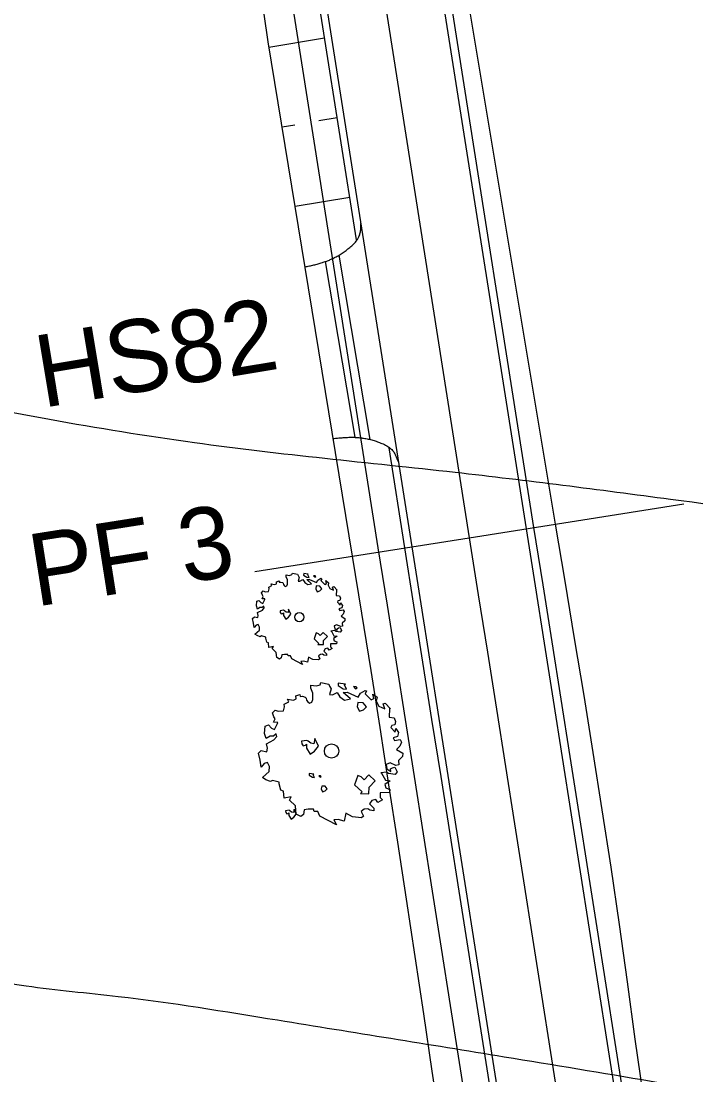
# Model space of a CAD drawing. Extents: x -477701 to -476785, y -1116511 to -1115314.
# Drawn here: x -477316.99 to -477293.68, y -1116152.79 to -1116116.39 of the extents above; entities that cross this region are included whole.
import ezdxf

# ---------------------------------------------------------------- set-up
doc = ezdxf.new("R2010")
doc.units = 0
for name, color, linetype in [('hrana_P', 7, 'Continuous'), ('hrana_R', 7, 'Continuous'), ('IP_RBK', 7, 'Continuous'), ('POLYGONY_SITUACE_PF', 7, 'Continuous'), ('POLYGONY_SITUACE_PF_POPISY', 7, 'Continuous'), ('popis', 7, 'Continuous'), ('svahování', 7, 'Continuous'), ('TP_HS', 7, 'Continuous'), ('Vrstevnice_hlavni', 7, 'Continuous'), ('Vrstevnice_vedlejsi', 7, 'Continuous')]:
    doc.layers.add(name, color=color, linetype=linetype)

msp = doc.modelspace()

# ---------------------------------------------------------------- linework, layer by layer
at = {"layer": 'hrana_P'}
for points in [[(-477308.462, -1116117.111), (-477310.173, -1116105.232)], [(-477298.532, -1116133.768), (-477301.498, -1116116.013)], [(-477305.541, -1116134.873), (-477308.462, -1116117.111)], [(-477298.196, -1116135.739), (-477298.532, -1116133.768)], [(-477305.218, -1116136.846), (-477305.541, -1116134.873)], [(-477297.882, -1116137.715), (-477298.196, -1116135.739)], [(-477304.905, -1116138.822), (-477305.218, -1116136.846)], [(-477297.547, -1116139.686), (-477297.882, -1116137.715)], [(-477304.593, -1116140.797), (-477304.905, -1116138.822)], [(-477297.23, -1116141.661), (-477297.547, -1116139.686)], [(-477304.289, -1116142.774), (-477304.593, -1116140.797)], [(-477296.917, -1116143.637), (-477297.23, -1116141.661)], [(-477303.984, -1116144.751), (-477304.289, -1116142.774)], [(-477296.617, -1116145.614), (-477296.917, -1116143.637)], [(-477303.678, -1116146.727), (-477303.984, -1116144.751)], [(-477296.328, -1116147.593), (-477296.617, -1116145.614)], [(-477303.378, -1116148.704), (-477303.678, -1116146.727)], [(-477296.045, -1116149.573), (-477296.328, -1116147.593)], [(-477303.079, -1116150.682), (-477303.378, -1116148.704)], [(-477295.781, -1116151.556), (-477296.045, -1116149.573)], [(-477302.79, -1116152.661), (-477303.079, -1116150.682)], [(-477293.766, -1116165.412), (-477295.781, -1116151.556)], [(-477300.647, -1116166.496), (-477302.79, -1116152.661)]]:
    msp.add_lwpolyline(points, dxfattribs=at)
at = {"layer": 'hrana_R'}
for points in [[(-477306.183, -1116104.603), (-477304.314, -1116116.457)], [(-477307.456, -1116116.807), (-477309.324, -1116104.954)], [(-477306.537, -1116116.807), (-477308.405, -1116104.954)], [(-477306.29, -1116116.768), (-477308.159, -1116104.915)], [(-477302.092, -1116116.107), (-477299.289, -1116133.887)], [(-477304.314, -1116116.457), (-477301.511, -1116134.237)], [(-477299.536, -1116133.926), (-477302.339, -1116116.145)], [(-477304.653, -1116134.588), (-477307.456, -1116116.807)], [(-477305.412, -1116123.945), (-477306.537, -1116116.807)], [(-477303.487, -1116134.549), (-477306.29, -1116116.768)], [(-477303.734, -1116134.588), (-477304.279, -1116131.133)], [(-477299.224, -1116135.901), (-477299.536, -1116133.926)], [(-477299.289, -1116133.887), (-477298.977, -1116135.863)], [(-477301.511, -1116134.237), (-477301.2, -1116136.213)], [(-477304.341, -1116136.563), (-477304.653, -1116134.588)], [(-477303.422, -1116136.563), (-477303.734, -1116134.588)], [(-477303.175, -1116136.524), (-477303.487, -1116134.549)], [(-477298.913, -1116137.877), (-477299.224, -1116135.901)], [(-477298.977, -1116135.863), (-477298.666, -1116137.838)], [(-477301.2, -1116136.213), (-477300.888, -1116138.189)], [(-477304.03, -1116138.539), (-477304.341, -1116136.563)], [(-477303.111, -1116138.539), (-477303.422, -1116136.563)], [(-477302.864, -1116138.5), (-477303.175, -1116136.524)], [(-477298.601, -1116139.853), (-477298.913, -1116137.877)], [(-477298.666, -1116137.838), (-477298.354, -1116139.814)], [(-477300.888, -1116138.189), (-477300.577, -1116140.164)], [(-477303.718, -1116140.514), (-477304.03, -1116138.539)], [(-477302.799, -1116140.514), (-477303.111, -1116138.539)], [(-477302.552, -1116140.476), (-477302.864, -1116138.5)], [(-477298.29, -1116141.828), (-477298.601, -1116139.853)], [(-477298.354, -1116139.814), (-477298.043, -1116141.789)], [(-477303.407, -1116142.49), (-477303.718, -1116140.514)], [(-477302.488, -1116142.49), (-477302.799, -1116140.514)], [(-477302.241, -1116142.451), (-477302.552, -1116140.476)], [(-477300.577, -1116140.164), (-477300.265, -1116142.14)], [(-477297.978, -1116143.804), (-477298.29, -1116141.828)], [(-477298.043, -1116141.789), (-477297.731, -1116143.765)], [(-477300.265, -1116142.14), (-477299.954, -1116144.115)], [(-477303.095, -1116144.466), (-477303.407, -1116142.49)], [(-477302.176, -1116144.466), (-477302.488, -1116142.49)], [(-477301.93, -1116144.427), (-477302.241, -1116142.451)], [(-477297.731, -1116143.765), (-477297.42, -1116145.741)], [(-477299.954, -1116144.115), (-477299.642, -1116146.091)], [(-477297.667, -1116145.779), (-477297.978, -1116143.804)], [(-477302.784, -1116146.441), (-477303.095, -1116144.466)], [(-477301.865, -1116146.441), (-477302.176, -1116144.466)], [(-477301.618, -1116146.402), (-477301.93, -1116144.427)], [(-477297.355, -1116147.755), (-477297.667, -1116145.779)], [(-477297.42, -1116145.741), (-477297.108, -1116147.716)], [(-477299.642, -1116146.091), (-477299.331, -1116148.067)], [(-477302.473, -1116148.417), (-477302.784, -1116146.441)], [(-477301.554, -1116148.417), (-477301.865, -1116146.441)], [(-477301.307, -1116148.378), (-477301.618, -1116146.402)], [(-477297.044, -1116149.731), (-477297.355, -1116147.755)], [(-477297.108, -1116147.716), (-477296.797, -1116149.692)], [(-477299.331, -1116148.067), (-477299.02, -1116150.042)], [(-477302.161, -1116150.392), (-477302.473, -1116148.417)], [(-477301.242, -1116150.392), (-477301.554, -1116148.417)], [(-477300.995, -1116150.354), (-477301.307, -1116148.378)], [(-477296.733, -1116151.706), (-477297.044, -1116149.731)], [(-477296.797, -1116149.692), (-477296.486, -1116151.667)], [(-477300.684, -1116152.329), (-477300.995, -1116150.354)], [(-477299.02, -1116150.042), (-477298.708, -1116152.018)], [(-477301.85, -1116152.368), (-477302.161, -1116150.392)], [(-477300.931, -1116152.368), (-477301.242, -1116150.392)], [(-477294.552, -1116165.535), (-477296.733, -1116151.706)], [(-477296.486, -1116151.667), (-477294.305, -1116165.497)], [(-477298.708, -1116152.018), (-477296.528, -1116165.847)], [(-477299.669, -1116166.197), (-477301.85, -1116152.368)], [(-477298.75, -1116166.197), (-477300.931, -1116152.368)], [(-477298.504, -1116166.158), (-477300.684, -1116152.329)]]:
    msp.add_lwpolyline(points, dxfattribs=at)
at = {"layer": 'IP_RBK'}
for points in [[(-477306.463, -1116135.72), (-477306.368, -1116135.793), (-477306.39, -1116135.875), (-477306.332, -1116135.988), (-477306.197, -1116136.05), (-477306.24, -1116135.94), (-477306.189, -1116135.925), (-477306.074, -1116136.049), (-477306.097, -1116136.041), (-477306.106, -1116136.231), (-477305.989, -1116136.244), (-477305.964, -1116136.327), (-477305.979, -1116136.403), (-477306.046, -1116136.419), (-477306.064, -1116136.464), (-477305.967, -1116136.562), (-477305.954, -1116136.483), (-477305.894, -1116136.574), (-477305.918, -1116136.66), (-477306.016, -1116136.693), (-477305.986, -1116136.753), (-477305.862, -1116136.726), (-477305.827, -1116136.786), (-477305.865, -1116136.873), (-477305.94, -1116136.946), (-477305.804, -1116137.028), (-477305.806, -1116137.107), (-477305.898, -1116137.19), (-477305.888, -1116137.289), (-477305.957, -1116137.305), (-477306.08, -1116137.246), (-477306.172, -1116137.277), (-477306.156, -1116137.379), (-477306.069, -1116137.433), (-477306.076, -1116137.379), (-477306.032, -1116137.355), (-477305.975, -1116137.343), (-477305.928, -1116137.442), (-477305.97, -1116137.499), (-477306.114, -1116137.479), (-477306.164, -1116137.447), (-477306.287, -1116137.464), (-477306.274, -1116137.469), (-477306.184, -1116137.629), (-477306.079, -1116137.643), (-477306.2, -1116137.721), (-477306.176, -1116137.799), (-477306.09, -1116137.835), (-477306.092, -1116137.897), (-477306.301, -1116137.908), (-477306.305, -1116138.01), (-477306.248, -1116138.06), (-477306.352, -1116138.12), (-477306.396, -1116138.055), (-477306.484, -1116138.076), (-477306.536, -1116138.155), (-477306.445, -1116138.25), (-477306.444, -1116138.306), (-477306.53, -1116138.293), (-477306.575, -1116138.263), (-477306.653, -1116138.267), (-477306.722, -1116138.32), (-477306.673, -1116138.422), (-477306.715, -1116138.46), (-477306.913, -1116138.439), (-477307.061, -1116138.361), (-477307.099, -1116138.535), (-477307.232, -1116138.499), (-477307.326, -1116138.51), (-477307.266, -1116138.618), (-477307.636, -1116138.426), (-477307.681, -1116138.322), (-477307.764, -1116138.318), (-477307.782, -1116138.27), (-477307.898, -1116138.268), (-477307.986, -1116138.285), (-477308.004, -1116138.385), (-477308.06, -1116138.43), (-477308.16, -1116138.379), (-477308.18, -1116138.197), (-477308.314, -1116138.068), (-477308.275, -1116137.996), (-477308.432, -1116138.025), (-477308.442, -1116137.868), (-477308.499, -1116137.85), (-477308.54, -1116137.706), (-477308.539, -1116137.672), (-477308.687, -1116137.632), (-477308.73, -1116137.657), (-477308.831, -1116137.619), (-477308.912, -1116137.568), (-477308.761, -1116137.433), (-477308.757, -1116137.326), (-477308.801, -1116137.235), (-477308.87, -1116137.257), (-477308.939, -1116137.339), (-477308.959, -1116137.186), (-477308.997, -1116137.027), (-477308.934, -1116136.972), (-477308.813, -1116136.998), (-477308.801, -1116136.919), (-477308.822, -1116136.822), (-477308.656, -1116136.736), (-477308.594, -1116136.663), (-477308.605, -1116136.603), (-477308.668, -1116136.652), (-477308.741, -1116136.652), (-477308.828, -1116136.706), (-477308.862, -1116136.594), (-477308.853, -1116136.432), (-477308.776, -1116136.401), (-477308.71, -1116136.478), (-477308.64, -1116136.504), (-477308.574, -1116136.369), (-477308.568, -1116136.346), (-477308.667, -1116136.345), (-477308.629, -1116136.269), (-477308.658, -1116136.222), (-477308.686, -1116136.139), (-477308.628, -1116136.073), (-477308.562, -1116136.102), (-477308.447, -1116136.091), (-477308.419, -1116136.002), (-477308.43, -1116135.947), (-477308.329, -1116135.89), (-477308.355, -1116135.831), (-477308.224, -1116135.858), (-477308.165, -1116135.825), (-477308.168, -1116135.758), (-477308.081, -1116135.729), (-477308.072, -1116135.774), (-477308.02, -1116135.77), (-477307.964, -1116135.787), (-477307.942, -1116135.811), (-477307.932, -1116135.854), (-477307.905, -1116135.892), (-477307.87, -1116135.919), (-477307.817, -1116135.904), (-477307.794, -1116135.84), (-477307.793, -1116135.698), (-477307.84, -1116135.589), (-477307.835, -1116135.522), (-477307.718, -1116135.542), (-477307.634, -1116135.513), (-477307.614, -1116135.463), (-477307.44, -1116135.502), (-477307.425, -1116135.546), (-477307.386, -1116135.607), (-477307.421, -1116135.734), (-477307.358, -1116135.739), (-477307.258, -1116135.682), (-477307.195, -1116135.784), (-477307.089, -1116135.854), (-477306.959, -1116135.827), (-477307.122, -1116135.684), (-477307.035, -1116135.676), (-477306.793, -1116135.789), (-477306.741, -1116135.703), (-477306.633, -1116135.639), (-477306.603, -1116135.652), (-477306.634, -1116135.718), (-477306.501, -1116135.849), (-477306.44, -1116135.821)], [(-477307.232, -1116135.533), (-477307.118, -1116135.605), (-477307.044, -1116135.614), (-477307.092, -1116135.515), (-477307.071, -1116135.5), (-477307.23, -1116135.477)], [(-477306.895, -1116135.554), (-477306.846, -1116135.605), (-477306.815, -1116135.581), (-477306.831, -1116135.558)], [(-477306.795, -1116135.905), (-477306.812, -1116136.005), (-477306.762, -1116136.102), (-477306.674, -1116136.069), (-477306.603, -1116136.002), (-477306.676, -1116135.914)], [(-477307.933, -1116136.829), (-477307.933, -1116136.92), (-477307.851, -1116137.049), (-477307.753, -1116136.987), (-477307.672, -1116136.875), (-477307.75, -1116136.709), (-477307.77, -1116136.821), (-477307.836, -1116136.81), (-477307.897, -1116136.765), (-477307.924, -1116136.745), (-477308.044, -1116136.76), (-477308.037, -1116136.82), (-477308.005, -1116136.869), (-477307.958, -1116136.85)], [(-477306.799, -1116137.524), (-477306.872, -1116137.734), (-477306.705, -1116137.888), (-477306.736, -1116137.923), (-477306.55, -1116137.927), (-477306.547, -1116137.786), (-477306.413, -1116137.644), (-477306.555, -1116137.51), (-477306.658, -1116137.618), (-477306.724, -1116137.556)], [(-477304.84, -1116139.637), (-477304.691, -1116139.75), (-477304.725, -1116139.879), (-477304.634, -1116140.055), (-477304.425, -1116140.151), (-477304.491, -1116139.98), (-477304.413, -1116139.956), (-477304.233, -1116140.15), (-477304.268, -1116140.138), (-477304.282, -1116140.434), (-477304.101, -1116140.455), (-477304.061, -1116140.584), (-477304.084, -1116140.702), (-477304.188, -1116140.727), (-477304.217, -1116140.797), (-477304.066, -1116140.95), (-477304.045, -1116140.826), (-477303.952, -1116140.969), (-477303.989, -1116141.103), (-477304.142, -1116141.153), (-477304.095, -1116141.247), (-477303.902, -1116141.205), (-477303.848, -1116141.299), (-477303.906, -1116141.435), (-477304.024, -1116141.548), (-477303.811, -1116141.677), (-477303.815, -1116141.799), (-477303.958, -1116141.929), (-477303.943, -1116142.084), (-477304.051, -1116142.108), (-477304.241, -1116142.017), (-477304.386, -1116142.065), (-477304.361, -1116142.224), (-477304.225, -1116142.308), (-477304.236, -1116142.224), (-477304.168, -1116142.187), (-477304.078, -1116142.168), (-477304.005, -1116142.321), (-477304.07, -1116142.41), (-477304.296, -1116142.38), (-477304.373, -1116142.33), (-477304.565, -1116142.357), (-477304.545, -1116142.365), (-477304.404, -1116142.613), (-477304.241, -1116142.635), (-477304.429, -1116142.758), (-477304.391, -1116142.878), (-477304.258, -1116142.934), (-477304.261, -1116143.032), (-477304.587, -1116143.049), (-477304.594, -1116143.208), (-477304.503, -1116143.286), (-477304.666, -1116143.379), (-477304.734, -1116143.278), (-477304.871, -1116143.31), (-477304.953, -1116143.434), (-477304.811, -1116143.581), (-477304.809, -1116143.669), (-477304.944, -1116143.648), (-477305.014, -1116143.602), (-477305.136, -1116143.608), (-477305.243, -1116143.691), (-477305.166, -1116143.85), (-477305.231, -1116143.91), (-477305.542, -1116143.877), (-477305.771, -1116143.755), (-477305.83, -1116144.025), (-477306.039, -1116143.97), (-477306.185, -1116143.987), (-477306.092, -1116144.155), (-477306.669, -1116143.856), (-477306.738, -1116143.694), (-477306.868, -1116143.688), (-477306.895, -1116143.613), (-477307.076, -1116143.61), (-477307.213, -1116143.636), (-477307.242, -1116143.793), (-477307.329, -1116143.863), (-477307.485, -1116143.783), (-477307.517, -1116143.499), (-477307.725, -1116143.298), (-477307.665, -1116143.186), (-477307.909, -1116143.23), (-477307.926, -1116142.986), (-477308.014, -1116142.958), (-477308.077, -1116142.734), (-477308.077, -1116142.681), (-477308.307, -1116142.618), (-477308.374, -1116142.657), (-477308.532, -1116142.598), (-477308.658, -1116142.518), (-477308.422, -1116142.308), (-477308.416, -1116142.141), (-477308.484, -1116141.998), (-477308.592, -1116142.034), (-477308.699, -1116142.161), (-477308.73, -1116141.922), (-477308.79, -1116141.676), (-477308.693, -1116141.589), (-477308.504, -1116141.63), (-477308.485, -1116141.506), (-477308.517, -1116141.355), (-477308.259, -1116141.222), (-477308.161, -1116141.108), (-477308.179, -1116141.013), (-477308.276, -1116141.09), (-477308.391, -1116141.09), (-477308.526, -1116141.175), (-477308.58, -1116141), (-477308.565, -1116140.747), (-477308.445, -1116140.699), (-477308.342, -1116140.82), (-477308.233, -1116140.86), (-477308.131, -1116140.649), (-477308.121, -1116140.614), (-477308.276, -1116140.611), (-477308.217, -1116140.494), (-477308.262, -1116140.42), (-477308.305, -1116140.29), (-477308.215, -1116140.188), (-477308.112, -1116140.232), (-477307.933, -1116140.215), (-477307.888, -1116140.076), (-477307.907, -1116139.991), (-477307.748, -1116139.903), (-477307.789, -1116139.81), (-477307.584, -1116139.853), (-477307.493, -1116139.801), (-477307.497, -1116139.696), (-477307.362, -1116139.651), (-477307.349, -1116139.722), (-477307.267, -1116139.715), (-477307.179, -1116139.741), (-477307.145, -1116139.78), (-477307.13, -1116139.846), (-477307.088, -1116139.906), (-477307.034, -1116139.947), (-477306.95, -1116139.923), (-477306.914, -1116139.824), (-477306.913, -1116139.603), (-477306.987, -1116139.433), (-477306.978, -1116139.329), (-477306.796, -1116139.359), (-477306.666, -1116139.315), (-477306.635, -1116139.237), (-477306.362, -1116139.298), (-477306.34, -1116139.366), (-477306.278, -1116139.461), (-477306.333, -1116139.658), (-477306.234, -1116139.666), (-477306.078, -1116139.578), (-477305.981, -1116139.737), (-477305.815, -1116139.846), (-477305.613, -1116139.803), (-477305.867, -1116139.58), (-477305.732, -1116139.568), (-477305.354, -1116139.745), (-477305.272, -1116139.61), (-477305.104, -1116139.51), (-477305.058, -1116139.531), (-477305.106, -1116139.634), (-477304.898, -1116139.838), (-477304.803, -1116139.794)], [(-477306.038, -1116139.345), (-477305.861, -1116139.458), (-477305.746, -1116139.472), (-477305.819, -1116139.318), (-477305.788, -1116139.294), (-477306.035, -1116139.259)], [(-477305.513, -1116139.379), (-477305.437, -1116139.458), (-477305.389, -1116139.42), (-477305.413, -1116139.385)], [(-477305.356, -1116139.925), (-477305.383, -1116140.082), (-477305.306, -1116140.232), (-477305.167, -1116140.18), (-477305.058, -1116140.076), (-477305.171, -1116139.939)], [(-477307.132, -1116141.365), (-477307.132, -1116141.508), (-477307.003, -1116141.71), (-477306.851, -1116141.613), (-477306.724, -1116141.438), (-477306.846, -1116141.178), (-477306.877, -1116141.354), (-477306.979, -1116141.336), (-477307.075, -1116141.266), (-477307.117, -1116141.236), (-477307.305, -1116141.259), (-477307.293, -1116141.353), (-477307.243, -1116141.429), (-477307.17, -1116141.399)], [(-477307.045, -1116142.441), (-477306.931, -1116142.513), (-477306.857, -1116142.522), (-477306.905, -1116142.423), (-477306.884, -1116142.408), (-477307.043, -1116142.385)], [(-477306.708, -1116142.462), (-477306.659, -1116142.513), (-477306.628, -1116142.488), (-477306.644, -1116142.466)], [(-477305.363, -1116142.449), (-477305.477, -1116142.777), (-477305.216, -1116143.018), (-477305.266, -1116143.071), (-477304.976, -1116143.078), (-477304.97, -1116142.858), (-477304.762, -1116142.637), (-477304.983, -1116142.428), (-477305.143, -1116142.597), (-477305.246, -1116142.499)], [(-477306.608, -1116142.813), (-477306.625, -1116142.913), (-477306.575, -1116143.009), (-477306.486, -1116142.976), (-477306.416, -1116142.91), (-477306.489, -1116142.822)], [(-477307.746, -1116143.736), (-477307.746, -1116143.828), (-477307.664, -1116143.957), (-477307.566, -1116143.895), (-477307.485, -1116143.783), (-477307.563, -1116143.616), (-477307.583, -1116143.729), (-477307.649, -1116143.718), (-477307.71, -1116143.673), (-477307.737, -1116143.653), (-477307.857, -1116143.668), (-477307.85, -1116143.728), (-477307.817, -1116143.777), (-477307.771, -1116143.758)]]:
    msp.add_lwpolyline(points, close=True, dxfattribs=at)
for centre, radius in [((-477307.38, -1116136.982), 0.158), ((-477306.269, -1116141.605), 0.247)]:
    msp.add_circle(centre, radius, dxfattribs=at)
at = {"layer": 'POLYGONY_SITUACE_PF'}
msp.add_lwpolyline([(-477308.92, -1116135.405), (-477301.511, -1116134.237), (-477294.103, -1116133.069)], dxfattribs=at)
at = {"layer": 'svahování'}
for points in [[(-477306.51, -1116116.981), (-477308.431, -1116117.303)], [(-477306.51, -1116116.981), (-477308.431, -1116117.303)], [(-477306.51, -1116116.981), (-477308.431, -1116117.303)], [(-477306.076, -1116119.733), (-477306.711, -1116119.84)], [(-477306.076, -1116119.733), (-477306.711, -1116119.84)], [(-477306.076, -1116119.733), (-477306.711, -1116119.84)], [(-477307.978, -1116120.052), (-477307.534, -1116119.978)], [(-477307.978, -1116120.052), (-477307.534, -1116119.978)], [(-477307.978, -1116120.052), (-477307.534, -1116119.978)], [(-477305.642, -1116122.486), (-477307.526, -1116122.802)], [(-477305.642, -1116122.486), (-477307.526, -1116122.802)], [(-477305.642, -1116122.486), (-477307.526, -1116122.802)]]:
    msp.add_lwpolyline(points, dxfattribs=at)
at = {"layer": 'TP_HS'}
for p, q in [((-477306.017, -1116124.484), (-477304.943, -1116130.843)), ((-477306.487, -1116124.701), (-477305.462, -1116130.77))]:
    msp.add_line(p, q, dxfattribs=at)
for points in [[(-477307.184, -1116124.88), (-477307.032, -1116124.853), (-477306.882, -1116124.817), (-477306.733, -1116124.776), (-477306.584, -1116124.732), (-477306.462, -1116124.692), (-477306.343, -1116124.646), (-477306.226, -1116124.593), (-477306.168, -1116124.565), (-477306.111, -1116124.536), (-477305.967, -1116124.454), (-477305.831, -1116124.363), (-477305.7, -1116124.263), (-477305.636, -1116124.21), (-477305.572, -1116124.156), (-477305.504, -1116124.093), (-477305.442, -1116124.027), (-477305.387, -1116123.955), (-477305.362, -1116123.916), (-477305.339, -1116123.874), (-477305.286, -1116123.744), (-477305.262, -1116123.608), (-477305.251, -1116123.38)], [(-477306.208, -1116130.814), (-477306.137, -1116130.804), (-477305.983, -1116130.788), (-477305.829, -1116130.778), (-477305.751, -1116130.774), (-477305.673, -1116130.77), (-477305.545, -1116130.768), (-477305.418, -1116130.773), (-477305.29, -1116130.784), (-477305.226, -1116130.791), (-477305.162, -1116130.8), (-477304.999, -1116130.83), (-477304.841, -1116130.871), (-477304.685, -1116130.922), (-477304.607, -1116130.951), (-477304.528, -1116130.982), (-477304.443, -1116131.019), (-477304.363, -1116131.061), (-477304.287, -1116131.111), (-477304.251, -1116131.139), (-477304.216, -1116131.171), (-477304.166, -1116131.221), (-477304.144, -1116131.248), (-477304.122, -1116131.277), (-477304.055, -1116131.397), (-477303.969, -1116131.608)]]:
    msp.add_spline(points, degree=3, dxfattribs=at)
at = {"layer": 'Vrstevnice_hlavni'}
msp.add_spline([(-477452.529, -1116145.839), (-477444.17, -1116138.201), (-477440.254, -1116135.19), (-477436.6, -1116132.987), (-477433.209, -1116131.591), (-477427.635, -1116129.786), (-477419.879, -1116127.572), (-477409.939, -1116124.948), (-477400.721, -1116122.941), (-477392.222, -1116121.549), (-477384.444, -1116120.775), (-477377.407, -1116120.116), (-477371.111, -1116119.574), (-477365.556, -1116119.147), (-477361.402, -1116119.005), (-477358.65, -1116119.147), (-477357.3, -1116119.574), (-477352.406, -1116120.961), (-477343.967, -1116123.308), (-477331.984, -1116126.616), (-477320.995, -1116129.164), (-477311.001, -1116130.95), (-477302.001, -1116131.976), (-477294.557, -1116132.905), (-477288.668, -1116133.736), (-477284.334, -1116134.47), (-477279.27, -1116135.445), (-477273.476, -1116136.66), (-477266.951, -1116138.117), (-477260.332, -1116139.255), (-477253.618, -1116140.076), (-477246.809, -1116140.58), (-477239.821, -1116142.182), (-477232.654, -1116144.883), (-477217.962, -1116152.484)], degree=3, dxfattribs=at)
at = {"layer": 'Vrstevnice_vedlejsi'}
for points in [[(-477151.618, -1116179.631), (-477155.809, -1116171.834), (-477158.79, -1116166.375), (-477160.561, -1116163.253), (-477161.122, -1116162.468), (-477161.68, -1116161.758), (-477162.236, -1116161.122), (-477162.789, -1116160.561), (-477165.506, -1116158.462), (-477170.386, -1116154.825), (-477177.431, -1116149.65), (-477183.852, -1116145.1), (-477189.65, -1116141.173), (-477194.825, -1116137.87), (-477201.827, -1116134.05), (-477210.655, -1116129.712), (-477221.309, -1116124.856), (-477229.305, -1116121.422), (-477234.643, -1116119.409), (-477237.321, -1116118.819), (-477239.326, -1116118.402), (-477240.658, -1116118.161), (-477241.316, -1116118.093), (-477245.98, -1116117.867), (-477254.649, -1116117.481), (-477267.325, -1116116.937), (-477279.509, -1116116.264), (-477291.201, -1116115.463), (-477302.403, -1116114.534), (-477310.581, -1116113.699), (-477315.736, -1116112.958), (-477317.868, -1116112.311), (-477321.057, -1116111.038), (-477325.304, -1116109.139), (-477330.608, -1116106.613), (-477336.821, -1116104.084), (-477343.941, -1116101.552), (-477351.971, -1116099.016), (-477359.307, -1116097.478), (-477365.95, -1116096.937), (-477367.437, -1116097.001), (-477368.925, -1116097.163), (-477370.413, -1116097.326), (-477371.9, -1116097.393), (-477378.328, -1116096.882), (-477385.233, -1116095.402), (-477387.09, -1116094.828), (-477388.919, -1116094.17), (-477390.75, -1116093.516), (-477392.617, -1116092.953), (-477400.49, -1116091.648), (-477408.852, -1116091.485), (-477417.704, -1116092.464), (-477425.098, -1116093.653), (-477431.035, -1116095.05), (-477435.514, -1116096.655), (-477441.673, -1116100.142), (-477449.512, -1116105.51), (-477459.031, -1116112.76), (-477466.649, -1116118.712), (-477472.366, -1116123.366), (-477476.183, -1116126.723), (-477479.467, -1116130.704), (-477480.559, -1116132.314)], [(-477199.82, -1116204.007), (-477200.739, -1116202.514), (-477201.27, -1116201.82), (-477201.875, -1116201.179), (-477202.552, -1116200.589), (-477207.089, -1116196.656), (-477215.486, -1116189.38), (-477227.743, -1116178.759), (-477238.175, -1116170.775), (-477246.781, -1116165.426), (-477253.562, -1116162.713), (-477260.267, -1116160.417), (-477266.895, -1116158.537), (-477273.448, -1116157.075), (-477281.2, -1116155.527), (-477290.151, -1116153.893), (-477300.303, -1116152.173), (-477308.131, -1116150.906), (-477313.636, -1116150.091), (-477316.818, -1116149.728), (-477320.571, -1116149.036), (-477324.896, -1116148.014), (-477329.793, -1116146.662), (-477335.87, -1116145.7), (-477343.126, -1116145.128), (-477351.563, -1116144.945), (-477360.546, -1116145.429), (-477370.073, -1116146.581), (-477380.147, -1116148.401), (-477387.949, -1116149.722), (-477393.48, -1116150.545), (-477396.74, -1116150.87), (-477399.688, -1116151.291), (-477402.323, -1116151.808), (-477404.646, -1116152.421), (-477408.076, -1116153.604), (-477412.612, -1116155.356), (-477418.255, -1116157.678), (-477423.245, -1116160.053), (-477427.583, -1116162.482), (-477431.268, -1116164.964), (-477433.964, -1116166.824), (-477435.672, -1116168.061), (-477436.392, -1116168.675), (-477437.552, -1116170.019), (-477439.151, -1116172.092), (-477441.189, -1116174.894), (-477442.91, -1116177.326), (-477444.315, -1116179.388), (-477445.403, -1116181.079), (-477446.061, -1116182.396), (-477446.29, -1116183.339), (-477446.09, -1116183.907), (-477445.933, -1116184.419), (-477445.817, -1116184.875), (-477445.745, -1116185.274), (-477445.711, -1116185.587), (-477445.716, -1116185.814), (-477445.759, -1116185.955), (-477446.027, -1116186.053), (-477446.522, -1116186.11), (-477447.242, -1116186.125), (-477448.164, -1116186.21), (-477449.287, -1116186.365), (-477450.611, -1116186.591), (-477451.625, -1116186.841), (-477452.328, -1116187.116), (-477452.721, -1116187.414), (-477453.447, -1116187.653), (-477454.505, -1116187.832), (-477455.895, -1116187.952), (-477457.34, -1116187.983), (-477458.839, -1116187.924), (-477460.392, -1116187.776), (-477461.247, -1116187.707)]]:
    msp.add_spline(points, degree=3, dxfattribs=at)

# ---------------------------------------------------------------- texts
at = {"layer": 'POLYGONY_SITUACE_PF_POPISY'}
msp.add_text('PF 3', height=2.5, rotation=8.9589, dxfattribs=at).set_placement((-477316.489, -1116136.623))
at = {"layer": 'popis'}
msp.add_text('HS82', height=2.5, rotation=9.4165, dxfattribs=at).set_placement((-477316.251, -1116129.756))

doc.saveas('drawing.dxf')
